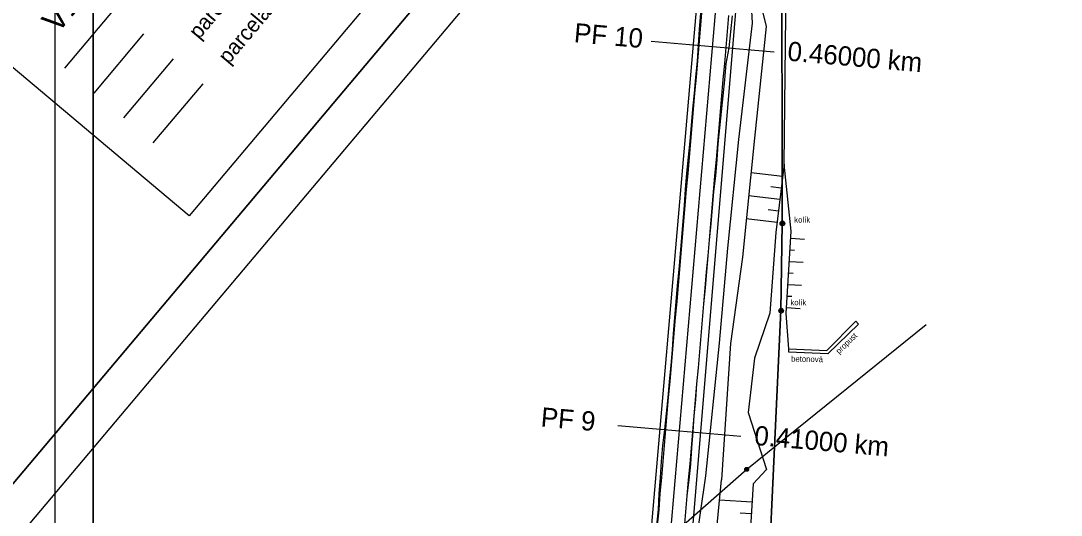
# Model space of a CAD drawing. Extents: x -555887 to -552101, y -1100251 to -1096546.
# Drawn here: x -554318 to -554183.3, y -1097197.3 to -1097133.2 of the extents above; entities that cross this region are included whole.
import ezdxf

# ---------------------------------------------------------------- set-up
doc = ezdxf.new("R2010")
doc.units = 0
for name, color, linetype in [('07_ELEKTRO', 7, 'Continuous'), ('PARCELY_cesty', 7, 'Continuous'), ('PARCELY_VHO', 7, 'Continuous'), ('POLYGONY_SITUACE_PF', 7, 'Continuous'), ('POLYGONY_SITUACE_PF_POPISY', 7, 'Continuous'), ('POLYGONY_SITUACE_PO', 7, 'Continuous'), ('ram_VC2', 7, 'Continuous'), ('ram_VC6', 7, 'Continuous'), ('ZSST', 7, 'Continuous'), ('zájem', 7, 'Continuous')]:
    doc.layers.add(name, color=color, linetype=linetype)

msp = doc.modelspace()

# ---------------------------------------------------------------- linework, layer by layer
at = {"layer": '07_ELEKTRO'}
msp.add_lwpolyline([(-554539.22, -1097146.24), (-554536.82, -1097177.88), (-554480.45, -1097188.3), (-554412.13, -1097200.87), (-554343.77, -1097213.15), (-554275.08, -1097225.88), (-554265.04, -1097227.44), (-554238.97, -1097204.45), (-554224, -1097191.31), (-554200.75, -1097172.55)], dxfattribs=at)
at = {"layer": 'PARCELY_cesty'}
for points in [[(-554222.14, -1097577.67), (-554219.8, -1097564.76), (-554214.88, -1097501.33), (-554212.93, -1097411.07), (-554213.82, -1097399.02), (-554215.27, -1097391.19), (-554218.76, -1097379.64), (-554223.52, -1097368.5), (-554249.09, -1097318.38), (-554253.81, -1097306), (-554255.45, -1097297.23), (-554257.68, -1097277.56), (-554257.68, -1097272.96), (-554254.78, -1097263.93), (-554248.28, -1097256.84), (-554243.38, -1097252.09), (-554241.28, -1097247.99), (-554240.16, -1097243.28), (-554227.33, -1097094.83)], [(-554213.98, -1097572.5), (-554209.03, -1097510.35), (-554207.05, -1097405.63), (-554208.48, -1097387.75), (-554231.63, -1097341.59), (-554244.51, -1097316.35), (-554248.98, -1097304.64), (-554250.5, -1097296.49), (-554252.68, -1097277.28), (-554252.68, -1097273.74), (-554250.86, -1097269.06), (-554235.26, -1097250.21), (-554222.33, -1097095.1)]]:
    msp.add_lwpolyline(points, dxfattribs=at)
at = {"layer": 'PARCELY_VHO'}
msp.add_lwpolyline([(-554219.47, -1097120.44), (-554219.42, -1097159.44), (-554219.57, -1097170.73), (-554221.23, -1097206.15), (-554219.79, -1097255.72), (-554235.35, -1097262.32), (-554235.26, -1097250.21), (-554222.33, -1097095.1)], dxfattribs=at)
at = {"layer": 'POLYGONY_SITUACE_PF'}
for p, q in [((-554236.39, -1097135.8), (-554228.42, -1097136.49)), ((-554228.42, -1097136.49), (-554220.45, -1097137.18)), ((-554240.69, -1097185.62), (-554232.72, -1097186.31)), ((-554232.72, -1097186.31), (-554224.75, -1097187))]:
    msp.add_line(p, q, dxfattribs=at)
at = {"layer": 'POLYGONY_SITUACE_PO'}
for p, q in [((-554237.68, -1097243.68), (-554224.83, -1097094.97)), ((-554230.11, -1097134.26), (-554229.93, -1097132.18)), ((-554229.98, -1097134.27), (-554229.8, -1097132.19)), ((-554229.98, -1097134.27), (-554229.8, -1097132.19)), ((-554226.5, -1097134.57), (-554226.32, -1097132.49)), ((-554226.5, -1097134.57), (-554226.32, -1097132.49)), ((-554226.07, -1097134.61), (-554225.86, -1097132.53)), ((-554230.23, -1097136.34), (-554230.11, -1097134.26)), ((-554230.16, -1097136.34), (-554229.98, -1097134.27)), ((-554230.16, -1097136.34), (-554229.98, -1097134.27)), ((-554226.67, -1097136.64), (-554226.5, -1097134.57)), ((-554226.67, -1097136.64), (-554226.5, -1097134.57)), ((-554226.28, -1097136.68), (-554226.07, -1097134.61)), ((-554230.36, -1097138.42), (-554230.23, -1097136.34)), ((-554230.34, -1097138.42), (-554230.16, -1097136.34)), ((-554230.34, -1097138.42), (-554230.16, -1097136.34)), ((-554226.85, -1097138.72), (-554226.67, -1097136.64)), ((-554226.85, -1097138.72), (-554226.67, -1097136.64)), ((-554226.67, -1097138.74), (-554226.28, -1097136.68)), ((-554230.57, -1097140.49), (-554230.36, -1097138.42)), ((-554230.52, -1097140.49), (-554230.34, -1097138.42)), ((-554230.52, -1097140.49), (-554230.34, -1097138.42)), ((-554227.03, -1097140.8), (-554226.85, -1097138.72)), ((-554227.03, -1097140.8), (-554226.85, -1097138.72)), ((-554226.84, -1097140.81), (-554226.67, -1097138.74)), ((-554230.77, -1097142.56), (-554230.57, -1097140.49)), ((-554230.7, -1097142.57), (-554230.52, -1097140.49)), ((-554230.7, -1097142.57), (-554230.52, -1097140.49)), ((-554227.21, -1097142.87), (-554227.03, -1097140.8)), ((-554227.21, -1097142.87), (-554227.03, -1097140.8)), ((-554227.03, -1097142.89), (-554226.84, -1097140.81)), ((-554230.97, -1097144.64), (-554230.77, -1097142.56)), ((-554230.88, -1097144.65), (-554230.7, -1097142.57)), ((-554230.88, -1097144.65), (-554230.7, -1097142.57)), ((-554227.39, -1097144.95), (-554227.21, -1097142.87)), ((-554227.39, -1097144.95), (-554227.21, -1097142.87)), ((-554227.25, -1097144.96), (-554227.03, -1097142.89)), ((-554231.14, -1097146.71), (-554230.97, -1097144.64)), ((-554231.06, -1097146.72), (-554230.88, -1097144.65)), ((-554231.06, -1097146.72), (-554230.88, -1097144.65)), ((-554227.57, -1097147.02), (-554227.39, -1097144.95)), ((-554227.57, -1097147.02), (-554227.39, -1097144.95)), ((-554227.48, -1097147.03), (-554227.25, -1097144.96)), ((-554231.32, -1097148.79), (-554231.14, -1097146.71)), ((-554231.24, -1097148.8), (-554231.06, -1097146.72)), ((-554231.24, -1097148.8), (-554231.06, -1097146.72)), ((-554227.75, -1097149.1), (-554227.57, -1097147.02)), ((-554227.75, -1097149.1), (-554227.57, -1097147.02)), ((-554227.7, -1097149.1), (-554227.48, -1097147.03)), ((-554231.53, -1097150.86), (-554231.32, -1097148.79)), ((-554231.42, -1097150.87), (-554231.24, -1097148.8)), ((-554231.42, -1097150.87), (-554231.24, -1097148.8)), ((-554227.93, -1097151.17), (-554227.75, -1097149.1)), ((-554227.93, -1097151.17), (-554227.75, -1097149.1)), ((-554227.84, -1097151.18), (-554227.7, -1097149.1)), ((-554231.74, -1097152.93), (-554231.53, -1097150.86)), ((-554231.6, -1097152.95), (-554231.42, -1097150.87)), ((-554231.6, -1097152.95), (-554231.42, -1097150.87)), ((-554228.11, -1097153.25), (-554227.93, -1097151.17)), ((-554228.11, -1097153.25), (-554227.93, -1097151.17)), ((-554228.02, -1097153.26), (-554227.84, -1097151.18)), ((-554231.94, -1097155.01), (-554231.74, -1097152.93)), ((-554231.78, -1097155.02), (-554231.6, -1097152.95)), ((-554231.78, -1097155.02), (-554231.6, -1097152.95)), ((-554228.29, -1097155.32), (-554228.11, -1097153.25)), ((-554228.29, -1097155.32), (-554228.11, -1097153.25)), ((-554228.26, -1097155.33), (-554228.02, -1097153.26)), ((-554232.07, -1097157.09), (-554231.94, -1097155.01)), ((-554231.96, -1097157.1), (-554231.78, -1097155.02)), ((-554231.96, -1097157.1), (-554231.78, -1097155.02)), ((-554228.47, -1097157.4), (-554228.29, -1097155.32)), ((-554228.47, -1097157.4), (-554228.29, -1097155.32)), ((-554228.44, -1097157.4), (-554228.26, -1097155.33)), ((-554232.25, -1097159.16), (-554232.07, -1097157.09)), ((-554232.14, -1097159.17), (-554231.96, -1097157.1)), ((-554232.14, -1097159.17), (-554231.96, -1097157.1)), ((-554228.65, -1097159.48), (-554228.47, -1097157.4)), ((-554228.65, -1097159.48), (-554228.47, -1097157.4)), ((-554228.62, -1097159.48), (-554228.44, -1097157.4)), ((-554232.41, -1097161.24), (-554232.25, -1097159.16)), ((-554232.31, -1097161.25), (-554232.14, -1097159.17)), ((-554232.31, -1097161.25), (-554232.14, -1097159.17)), ((-554228.83, -1097161.55), (-554228.65, -1097159.48)), ((-554228.83, -1097161.55), (-554228.65, -1097159.48)), ((-554228.82, -1097161.55), (-554228.62, -1097159.48)), ((-554232.56, -1097163.32), (-554232.41, -1097161.24)), ((-554232.49, -1097163.33), (-554232.31, -1097161.25)), ((-554232.49, -1097163.33), (-554232.31, -1097161.25)), ((-554229.01, -1097163.63), (-554228.83, -1097161.55)), ((-554229.01, -1097163.63), (-554228.83, -1097161.55)), ((-554228.98, -1097163.63), (-554228.82, -1097161.55)), ((-554232.77, -1097165.39), (-554232.56, -1097163.32)), ((-554232.67, -1097165.4), (-554232.49, -1097163.33)), ((-554232.67, -1097165.4), (-554232.49, -1097163.33)), ((-554229.19, -1097165.7), (-554229.01, -1097163.63)), ((-554229.19, -1097165.7), (-554229.01, -1097163.63)), ((-554229.18, -1097165.7), (-554228.98, -1097163.63)), ((-554232.96, -1097167.47), (-554232.77, -1097165.39)), ((-554232.85, -1097167.48), (-554232.67, -1097165.4)), ((-554232.85, -1097167.48), (-554232.67, -1097165.4)), ((-554229.37, -1097167.78), (-554229.19, -1097165.7)), ((-554229.37, -1097167.78), (-554229.19, -1097165.7)), ((-554229.34, -1097167.78), (-554229.18, -1097165.7)), ((-554233.15, -1097169.54), (-554232.96, -1097167.47)), ((-554233.03, -1097169.55), (-554232.85, -1097167.48)), ((-554233.03, -1097169.55), (-554232.85, -1097167.48)), ((-554229.55, -1097169.85), (-554229.37, -1097167.78)), ((-554229.55, -1097169.85), (-554229.37, -1097167.78)), ((-554229.55, -1097169.85), (-554229.34, -1097167.78)), ((-554233.33, -1097171.62), (-554233.15, -1097169.54)), ((-554233.21, -1097171.63), (-554233.03, -1097169.55)), ((-554233.21, -1097171.63), (-554233.03, -1097169.55)), ((-554229.72, -1097171.93), (-554229.55, -1097169.85)), ((-554229.72, -1097171.93), (-554229.55, -1097169.85)), ((-554229.72, -1097171.93), (-554229.55, -1097169.85)), ((-554229.55, -1097169.85), (-554229.55, -1097169.85)), ((-554233.48, -1097173.7), (-554233.33, -1097171.62)), ((-554233.39, -1097173.7), (-554233.21, -1097171.63)), ((-554233.39, -1097173.7), (-554233.21, -1097171.63)), ((-554229.9, -1097174.01), (-554229.72, -1097171.93)), ((-554229.9, -1097174.01), (-554229.72, -1097171.93)), ((-554229.9, -1097174.01), (-554229.72, -1097171.93)), ((-554233.62, -1097175.77), (-554233.48, -1097173.7)), ((-554233.57, -1097175.78), (-554233.39, -1097173.7)), ((-554233.57, -1097175.78), (-554233.39, -1097173.7)), ((-554230.08, -1097176.08), (-554229.9, -1097174.01)), ((-554230.08, -1097176.08), (-554229.9, -1097174.01)), ((-554230.08, -1097176.08), (-554229.9, -1097174.01)), ((-554233.8, -1097177.85), (-554233.62, -1097175.77)), ((-554233.75, -1097177.85), (-554233.57, -1097175.78)), ((-554233.75, -1097177.85), (-554233.57, -1097175.78)), ((-554230.26, -1097178.16), (-554230.08, -1097176.08)), ((-554230.26, -1097178.16), (-554230.08, -1097176.08)), ((-554230.26, -1097178.16), (-554230.08, -1097176.08)), ((-554230.08, -1097176.08), (-554230.08, -1097176.08)), ((-554234, -1097179.92), (-554233.8, -1097177.85)), ((-554233.93, -1097179.93), (-554233.75, -1097177.85)), ((-554233.93, -1097179.93), (-554233.75, -1097177.85)), ((-554230.44, -1097180.23), (-554230.26, -1097178.16)), ((-554230.44, -1097180.23), (-554230.26, -1097178.16)), ((-554230.44, -1097180.23), (-554230.26, -1097178.16)), ((-554234.19, -1097182), (-554234, -1097179.92)), ((-554234.11, -1097182.01), (-554233.93, -1097179.93)), ((-554234.11, -1097182.01), (-554233.93, -1097179.93)), ((-554230.62, -1097182.31), (-554230.44, -1097180.23)), ((-554230.62, -1097182.31), (-554230.44, -1097180.23)), ((-554230.6, -1097182.31), (-554230.44, -1097180.23)), ((-554234.39, -1097184.07), (-554234.19, -1097182)), ((-554234.29, -1097184.08), (-554234.11, -1097182.01)), ((-554234.29, -1097184.08), (-554234.11, -1097182.01)), ((-554230.8, -1097184.38), (-554230.62, -1097182.31)), ((-554230.8, -1097184.38), (-554230.62, -1097182.31)), ((-554230.8, -1097184.38), (-554230.6, -1097182.31)), ((-554234.62, -1097186.14), (-554234.39, -1097184.07)), ((-554234.47, -1097186.16), (-554234.29, -1097184.08)), ((-554234.47, -1097186.16), (-554234.29, -1097184.08)), ((-554230.98, -1097186.46), (-554230.8, -1097184.38)), ((-554230.98, -1097186.46), (-554230.8, -1097184.38)), ((-554230.93, -1097186.46), (-554230.8, -1097184.38)), ((-554230.8, -1097184.38), (-554230.8, -1097184.38)), ((-554230.8, -1097184.38), (-554230.8, -1097184.38)), ((-554234.88, -1097188.21), (-554234.62, -1097186.14)), ((-554234.65, -1097188.23), (-554234.47, -1097186.16)), ((-554234.65, -1097188.23), (-554234.47, -1097186.16)), ((-554231.16, -1097188.53), (-554230.98, -1097186.46)), ((-554231.16, -1097188.53), (-554230.98, -1097186.46)), ((-554231.09, -1097188.54), (-554230.93, -1097186.46)), ((-554235.04, -1097190.29), (-554234.88, -1097188.21)), ((-554234.83, -1097190.31), (-554234.65, -1097188.23)), ((-554234.83, -1097190.31), (-554234.65, -1097188.23)), ((-554231.34, -1097190.61), (-554231.16, -1097188.53)), ((-554231.34, -1097190.61), (-554231.16, -1097188.53)), ((-554231.26, -1097190.62), (-554231.09, -1097188.54)), ((-554235.18, -1097192.37), (-554235.04, -1097190.29)), ((-554235.01, -1097192.38), (-554234.83, -1097190.31)), ((-554235.01, -1097192.38), (-554234.83, -1097190.31)), ((-554231.52, -1097192.69), (-554231.34, -1097190.61)), ((-554231.52, -1097192.69), (-554231.34, -1097190.61)), ((-554231.45, -1097192.69), (-554231.26, -1097190.62)), ((-554235.32, -1097194.45), (-554235.18, -1097192.37)), ((-554235.19, -1097194.46), (-554235.01, -1097192.38)), ((-554235.19, -1097194.46), (-554235.01, -1097192.38)), ((-554231.7, -1097194.76), (-554231.52, -1097192.69)), ((-554231.7, -1097194.76), (-554231.52, -1097192.69)), ((-554231.7, -1097194.76), (-554231.45, -1097192.69)), ((-554235.44, -1097196.53), (-554235.32, -1097194.45)), ((-554235.36, -1097196.54), (-554235.19, -1097194.46)), ((-554235.36, -1097196.54), (-554235.19, -1097194.46)), ((-554231.88, -1097196.84), (-554231.7, -1097194.76)), ((-554231.88, -1097196.84), (-554231.7, -1097194.76)), ((-554231.88, -1097196.84), (-554231.7, -1097194.76)), ((-554231.7, -1097194.76), (-554231.7, -1097194.76)), ((-554235.63, -1097198.6), (-554235.44, -1097196.53)), ((-554235.54, -1097198.61), (-554235.36, -1097196.54)), ((-554235.54, -1097198.61), (-554235.36, -1097196.54)), ((-554232.06, -1097198.91), (-554231.88, -1097196.84)), ((-554232.06, -1097198.91), (-554231.88, -1097196.84)), ((-554232.06, -1097198.91), (-554231.88, -1097196.84))]:
    msp.add_line(p, q, dxfattribs=at)
at = {"layer": 'ram_VC2'}
for p, q in [((-554305.94, -1097131.66), (-554312.38, -1097139.31)), ((-554302.12, -1097134.88), (-554308.56, -1097142.53)), ((-554298.29, -1097138.1), (-554304.73, -1097145.75)), ((-554294.47, -1097141.32), (-554300.91, -1097148.97))]:
    msp.add_line(p, q, dxfattribs=at)
for points in [[(-554114.88, -1096958.27), (-554342.13, -1096767.04), (-555018.18, -1097570.44), (-554790.93, -1097761.67)], [(-554121.93, -1096958.88), (-554341.52, -1096774.09), (-555011.14, -1097569.84), (-554791.54, -1097754.63)], [(-554365.16, -1097100.42), (-554324.01, -1097051.52), (-554255.08, -1097109.53), (-554296.23, -1097158.43)]]:
    msp.add_lwpolyline(points, close=True, dxfattribs=at)
for points in [[(-554114.88, -1096958.27), (-554342.13, -1096767.04), (-555018.18, -1097570.44), (-554790.93, -1097761.67), (-554114.88, -1096958.27)], [(-554791.54, -1097754.63), (-555011.14, -1097569.84), (-554341.52, -1096774.09), (-554121.93, -1096958.88), (-554791.54, -1097754.63)]]:
    msp.add_lwpolyline(points, dxfattribs=at)
at = {"layer": 'ram_VC6'}
for points in [[(-553956.64, -1096765.72), (-554313.64, -1096765.72), (-554313.64, -1097395.72), (-553956.64, -1097395.72)], [(-553961.64, -1096770.72), (-554308.64, -1096770.72), (-554308.64, -1097390.72), (-553961.64, -1097390.72)]]:
    msp.add_lwpolyline(points, close=True, dxfattribs=at)
for points in [[(-553956.64, -1096765.72), (-554313.64, -1096765.72), (-554313.64, -1097395.72), (-553956.64, -1097395.72), (-553956.64, -1096765.72)], [(-553956.64, -1096765.72), (-554313.64, -1096765.72), (-554313.64, -1097395.72), (-553956.64, -1097395.72), (-553956.64, -1096765.72)], [(-553961.64, -1097390.72), (-554308.64, -1097390.72), (-554308.64, -1096770.72), (-553961.64, -1096770.72), (-553961.64, -1097390.72)], [(-553961.64, -1097185.72), (-553961.64, -1097390.72), (-554308.64, -1097390.72), (-554308.64, -1096770.72), (-553961.64, -1096770.72), (-553961.64, -1096975.72), (-553961.64, -1097185.72)]]:
    msp.add_lwpolyline(points, dxfattribs=at)
at = {"layer": 'ZSST'}
for p, q in [((-554219.35, -1097153.37), (-554223.44, -1097152.88)), ((-554219.53, -1097154.86), (-554220.88, -1097154.69)), ((-554219.71, -1097156.34), (-554223.75, -1097155.86)), ((-554219.88, -1097157.83), (-554221.22, -1097157.68)), ((-554220.06, -1097159.32), (-554224.05, -1097158.85)), ((-554218.29, -1097161.36), (-554216.52, -1097161.47)), ((-554218.38, -1097162.86), (-554217.79, -1097162.89)), ((-554218.47, -1097164.35), (-554216.7, -1097164.46)), ((-554218.56, -1097165.85), (-554217.97, -1097165.89)), ((-554218.65, -1097167.35), (-554216.89, -1097167.46)), ((-554218.74, -1097168.85), (-554218.15, -1097168.88)), ((-554218.83, -1097170.34), (-554217.07, -1097170.45)), ((-554209.88, -1097172.1), (-554209.54, -1097172.49)), ((-554229.09, -1097211.38), (-554227.27, -1097192.66)), ((-554223.32, -1097195.57), (-554227.53, -1097195.31)), ((-554223.41, -1097197.07), (-554224.83, -1097196.98))]:
    msp.add_line(p, q, dxfattribs=at)
for points in [[(-554218.54, -1097175.67), (-554218.88, -1097171.11), (-554218.23, -1097160.44), (-554219.16, -1097151.75), (-554218.79, -1097120.84), (-554218.38, -1097111.65), (-554216.83, -1097104.6), (-554216.54, -1097100.8), (-554217.26, -1097093.11), (-554218.21, -1097084.79), (-554219.72, -1097074.34), (-554228.66, -1097049.95), (-554233.75, -1097046.05), (-554234.74, -1097042.43), (-554239.98, -1097031.94), (-554247.7, -1097012.53), (-554248.49, -1097007.1), (-554246.97, -1096987.92), (-554248.9, -1096972.89), (-554248.75, -1096969.32)], [(-554232.17, -1097214.32), (-554232.2, -1097212.26), (-554229.31, -1097192.14), (-554227.51, -1097174.97), (-554226.45, -1097162.63), (-554225.01, -1097148.57), (-554223.27, -1097133.48), (-554223.72, -1097124.66)], [(-554223.72, -1097124.66), (-554221.49, -1097133.92), (-554222.99, -1097148.39), (-554224.55, -1097163.82), (-554226.09, -1097174.99), (-554227.27, -1097192.66)], [(-554219.16, -1097151.75), (-554220.21, -1097160.59), (-554221.02, -1097171.08), (-554222.98, -1097176.9), (-554223.81, -1097183.94), (-554221.44, -1097191.34), (-554223.18, -1097193.2), (-554223.91, -1097205.24), (-554224.85, -1097223.18), (-554226.44, -1097248.6), (-554221.11, -1097251.69), (-554217.1, -1097254.56)], [(-554238.97, -1097204.45), (-554224, -1097191.31), (-554200.75, -1097172.55)], [(-554209.54, -1097172.49), (-554213.51, -1097176.36), (-554218.56, -1097176.13), (-554218.54, -1097175.67), (-554213.62, -1097175.89), (-554209.88, -1097172.1)]]:
    msp.add_lwpolyline(points, dxfattribs=at)
for centre, radius in [((-554219.37, -1097159.43), 0.3), ((-554219.37, -1097159.43), 0.15), ((-554219.54, -1097170.75), 0.3), ((-554219.54, -1097170.75), 0.15), ((-554224, -1097191.31), 0.25), ((-554224, -1097191.31), 0.158), ((-554224, -1097191.31), 0.05)]:
    msp.add_circle(centre, radius, dxfattribs=at)
at = {"layer": 'zájem'}
for points in [[(-554219.47, -1097120.44), (-554219.42, -1097159.44), (-554219.57, -1097170.73), (-554221.23, -1097206.15), (-554219.79, -1097255.72), (-554247.32, -1097267.54), (-554250.86, -1097269.06), (-554245.31, -1097300.76), (-554223.69, -1097322.98), (-554209.05, -1097338.04), (-554121.59, -1097427.95)], [(-554121.59, -1097427.95), (-554209.05, -1097338.04), (-554223.69, -1097322.98), (-554245.31, -1097300.76), (-554250.86, -1097269.06), (-554247.32, -1097267.54), (-554219.79, -1097255.72), (-554221.23, -1097206.15), (-554219.57, -1097170.73), (-554219.42, -1097159.44), (-554219.47, -1097120.44)]]:
    msp.add_lwpolyline(points, dxfattribs=at)

# ---------------------------------------------------------------- texts
at = {"layer": 'POLYGONY_SITUACE_PF_POPISY'}
for s, p in [('PF 10', (-554246.44, -1097135.94)), ('0.46000 km', (-554218.79, -1097138.33)), ('PF 9', (-554250.74, -1097185.75)), ('0.41000 km', (-554223.09, -1097188.14))]:
    msp.add_text(s, height=2.5, rotation=355.0592, dxfattribs=at).set_placement(p)
at = {"layer": 'ram_VC2'}
for s, height, p in [('parcela silnice, místní komunikace', 2, (-554291.13, -1097138.9)), ('parcela interakčního prvku', 2, (-554294.95, -1097135.68)), ('V1', 3, (-554313.24, -1097134.89))]:
    msp.add_text(s, height=height, rotation=49.9197, dxfattribs=at).set_placement(p)
at = {"layer": 'ZSST'}
for p in [(-554217.84, -1097159.33), (-554218.34, -1097170.05)]:
    msp.add_text('kolík', height=0.75, dxfattribs=at).set_placement(p)
for s, rotation, p in [('propust', 44.2896, (-554212.02, -1097176.41)), ('betonová', 358.9581, (-554218.26, -1097177.35))]:
    msp.add_text(s, height=0.75, rotation=rotation, dxfattribs=at).set_placement(p)

doc.saveas('drawing.dxf')
